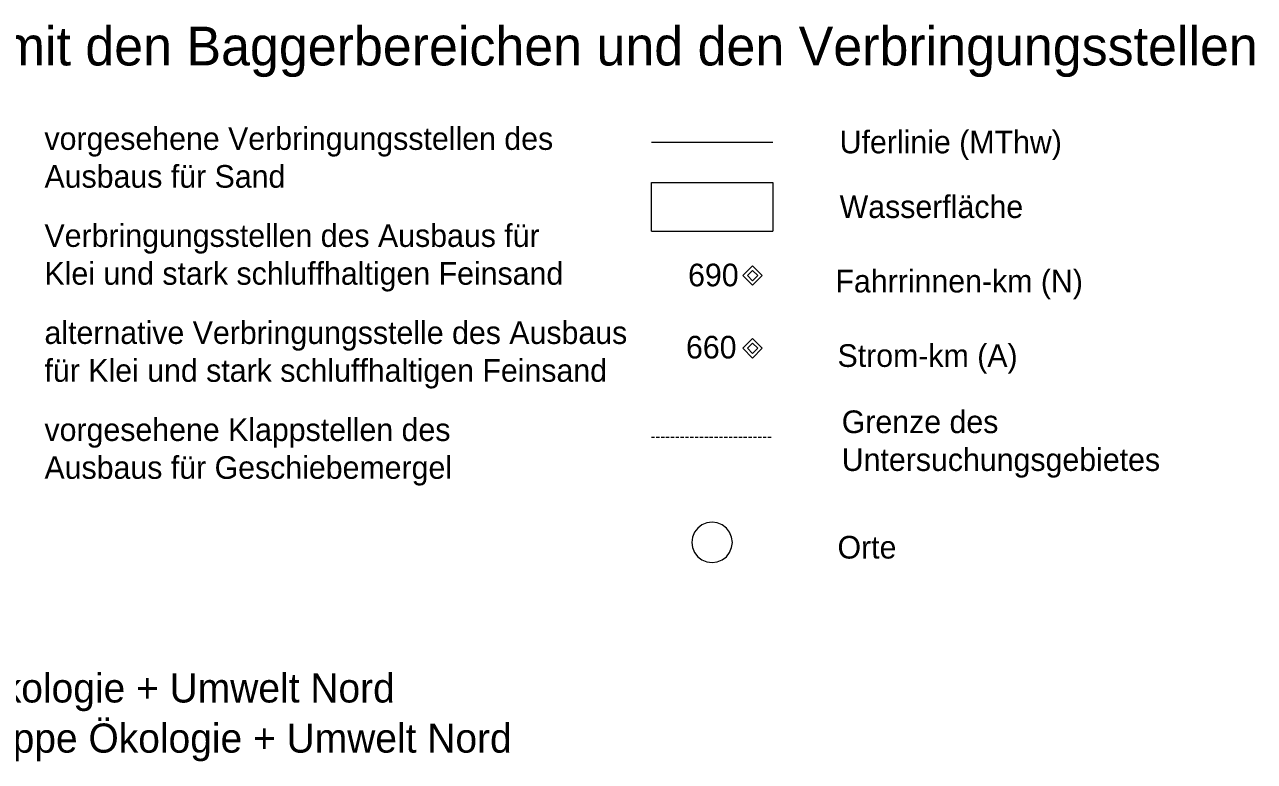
# Model space of a CAD drawing. Extents: x 3461750 to 3585707, y 5917729 to 5985917.
# Drawn here: x 3485386 to 3523380, y 5917729 to 5940508 of the extents above; entities that cross this region are included whole.
import ezdxf

# ---------------------------------------------------------------- set-up
doc = ezdxf.new("R2010")
doc.units = 0
doc.header["$LTSCALE"] = 80
doc.layers.add('16', color=7, linetype='Continuous', lineweight=13)

msp = doc.modelspace()

# ---------------------------------------------------------------- linework, layer by layer
at = {"layer": '16'}
for p, q in [((3504750, 5936875), (3508500, 5936875)), ((3504750, 5934125), (3508500, 5934125)), ((3504750, 5927750), (3504850, 5927750)), ((3504900, 5927750), (3505000, 5927750)), ((3505050, 5927750), (3505150, 5927750)), ((3505200, 5927750), (3505300, 5927750)), ((3505350, 5927750), (3505450, 5927750)), ((3505500, 5927750), (3505600, 5927750)), ((3505650, 5927750), (3505750, 5927750)), ((3505800, 5927750), (3505900, 5927750)), ((3505950, 5927750), (3506050, 5927750)), ((3506100, 5927750), (3506200, 5927750)), ((3506250, 5927750), (3506350, 5927750)), ((3506400, 5927750), (3506500, 5927750)), ((3506550, 5927750), (3506650, 5927750)), ((3506700, 5927750), (3506800, 5927750)), ((3506850, 5927750), (3506950, 5927750)), ((3507000, 5927750), (3507100, 5927750)), ((3507150, 5927750), (3507250, 5927750)), ((3507300, 5927750), (3507400, 5927750)), ((3507450, 5927750), (3507550, 5927750)), ((3507600, 5927750), (3507700, 5927750)), ((3507750, 5927750), (3507850, 5927750)), ((3507900, 5927750), (3508000, 5927750)), ((3508050, 5927750), (3508150, 5927750)), ((3508200, 5927750), (3508300, 5927750)), ((3508350, 5927750), (3508450, 5927750))]:
    msp.add_line(p, q, dxfattribs=at)
msp.add_lwpolyline([(3504750, 5934125), (3504750, 5935625), (3508500, 5935625), (3508500, 5934125)], dxfattribs=at)
for points in [[(3507874.76, 5933049.61), (3507574.37, 5932749.32), (3507874.76, 5932448.93), (3508175.1, 5932749.32)], [(3507874.76, 5932908.01), (3507715.97, 5932749.32), (3507874.76, 5932590.53), (3508033.5, 5932749.32)], [(3507874.76, 5930799.61), (3507574.37, 5930499.32), (3507874.76, 5930198.93), (3508175.1, 5930499.32)], [(3507874.76, 5930658.01), (3507715.97, 5930499.32), (3507874.76, 5930340.53), (3508033.5, 5930499.32)], [(3507258.72, 5924495.7), (3507229.43, 5924661.96), (3507166.92, 5924812.88), (3507067.47, 5924942.47), (3506937.88, 5925041.92), (3506786.96, 5925104.43), (3506625, 5925125.75), (3506463.04, 5925104.43), (3506312.12, 5925041.92), (3506182.53, 5924942.47), (3506083.08, 5924812.88), (3506020.57, 5924661.96), (3505999.25, 5924500), (3506020.57, 5924338.04), (3506083.08, 5924187.12), (3506182.53, 5924057.53), (3506312.12, 5923958.08), (3506463.04, 5923895.57), (3506625, 5923874.25), (3506786.96, 5923895.57), (3506937.88, 5923958.08), (3507067.47, 5924057.53), (3507166.92, 5924187.12), (3507229.43, 5924338.04)]]:
    msp.add_lwpolyline(points, close=True, dxfattribs=at)

# ---------------------------------------------------------------- texts
for s, height, p in [('Karte 3 - 1: Der Ausbaubereich mit den Baggerbereichen und den Verbringungsstellen ', 1200, (3462111.1, 5939244.4)), ('vorgesehene Verbringungsstellen des', 700, (3486000, 5936635)), ('Uferlinie (MThw)', 700, (3510566, 5936527.9)), ('Ausbaus für Sand', 700, (3486000, 5935465)), ('Wasserfläche', 700, (3510566, 5934527.9)), ('Verbringungsstellen des Ausbaus für', 700, (3486000, 5933635)), ('Klei und stark schluffhaltigen Feinsand', 700, (3486000, 5932465)), ('690', 700, (3505883.8, 5932416.6)), ('Fahrrinnen-km (N)', 700, (3510435.9, 5932226.8)), ('alternative Verbringungsstelle des Ausbaus', 700, (3486000, 5930635)), ('660', 700, (3505818.8, 5930185.3)), ('Strom-km (A)', 700, (3510500, 5929925)), ('für Klei und stark schluffhaltigen Feinsand', 700, (3486000, 5929465)), ('Grenze des', 700, (3510631, 5927878.9)), ('vorgesehene Klappstellen des', 700, (3486000, 5927635)), ('Ausbaus für Geschiebemergel', 700, (3486000, 5926465)), ('Untersuchungsgebietes', 700, (3510631, 5926708.9)), ('Orte', 700, (3510500, 5924000)), ('Fachliche Bearbeitung: Planungsgruppe Ökologie + Umwelt Nord', 900, (3462000, 5919550)), ('Kartographische Bearbeitung: Planungsgruppe Ökologie + Umwelt Nord', 900, (3462000, 5918000))]:
    msp.add_text(s, height=height, dxfattribs=at).set_placement(p)

doc.saveas('drawing.dxf')
